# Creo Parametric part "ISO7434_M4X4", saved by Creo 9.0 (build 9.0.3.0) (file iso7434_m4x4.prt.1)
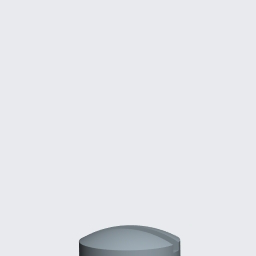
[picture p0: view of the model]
Units: Custom; MM, POUND, SECS

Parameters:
  BASIC_DIA = "4"
  PLACEMENT = "A"

Other parameters: D2, D11, D10, D0, D12, D1, THREADS_PER_INCH

Created from: ISO7434.PRT

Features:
  1. datum plane "DTM1"
  2. datum plane "DTM2"
  3. cut
  4. datum plane "DTM3"

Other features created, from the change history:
  component interface "Komponentenschnittstelle ID 162"

Other named items: THRU

Layers: 32, EBENEN, FLAECHEN, FLAECHENVERBUND, GEOM.ELEMENT, KONSTR.ELEMENT, NICHT.GEOM_ELEM

Surfaces: 4 cylinder, 3 plane, 2 torus, 2 cone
